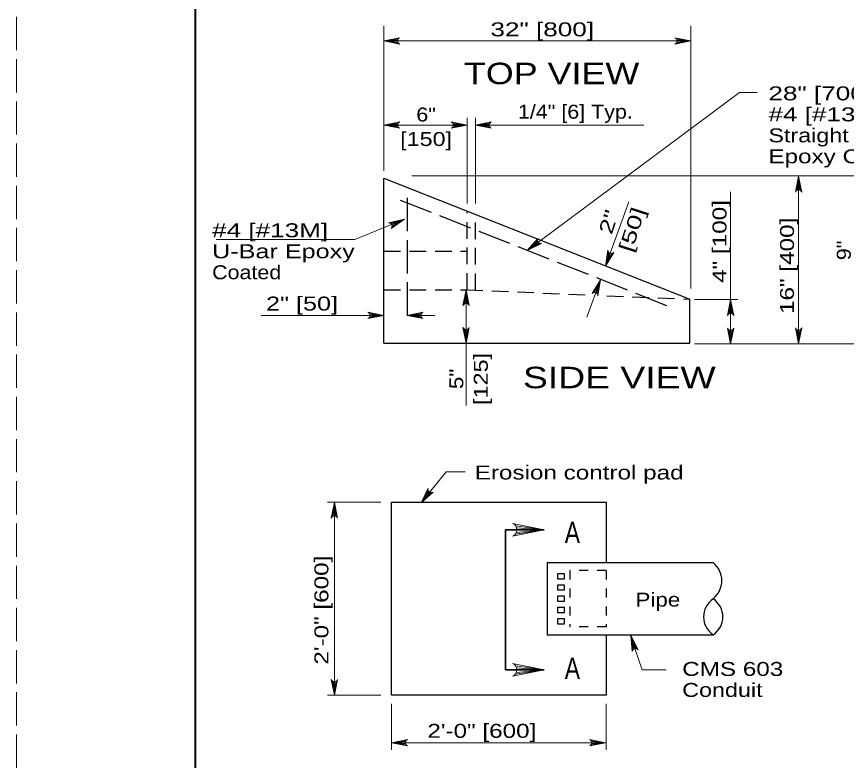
# Model space of a CAD drawing. Extents: x 1083.1 to 1117.1, y 697.4 to 741.4.
# Drawn here: x 1083.13 to 1092.41, y 728.79 to 737.11 of the extents above; entities that cross this region are included whole.
import ezdxf
from ezdxf.enums import TextEntityAlignment as Align

# ---------------------------------------------------------------- set-up
doc = ezdxf.new("R2010")
doc.units = 0
doc.header["$LTSCALE"] = 0.062
for name, pattern in [('LONG_DASHED', [7.5, 6, -1.5]), ('MEDIUM_DASHED', [4.5, 3, -1.5]), ('SHORT_DASHED', [2.7, 1.5, -1.2])]:
    doc.linetypes.add(name, pattern=pattern)
doc.layers.add('1', color=7, linetype='Continuous', lineweight=13)

msp = doc.modelspace()

# ---------------------------------------------------------------- linework, layer by layer
at = {"layer": '1'}
for p, q in [((1087.23608, 735.38583), (1087.23608, 737.00783)), ((1090.66825, 736.05733), (1090.66825, 737.00783)), ((1087.39633, 736.86058), (1087.23608, 736.83817)), ((1087.39092, 736.8495), (1087.23608, 736.83817)), ((1087.38925, 736.83817), (1087.23608, 736.83817)), ((1087.39208, 736.82383), (1087.23608, 736.83817)), ((1087.39825, 736.81342), (1087.23608, 736.83817)), ((1090.66825, 736.83817), (1087.23608, 736.83817)), ((1090.50608, 736.81342), (1090.66825, 736.83817)), ((1090.508, 736.86058), (1090.66825, 736.83817)), ((1090.51225, 736.82383), (1090.66825, 736.83817)), ((1090.51342, 736.8495), (1090.66825, 736.83817)), ((1090.51508, 736.83817), (1090.66825, 736.83817)), ((1088.16583, 735.02092), (1088.16583, 735.97592)), ((1088.2595, 735.02092), (1088.2595, 735.97592)), ((1090.66825, 734.07008), (1090.66825, 736.05733)), ((1087.39633, 735.91967), (1087.23608, 735.89725)), ((1087.39092, 735.90858), (1087.23608, 735.89725)), ((1087.38925, 735.89725), (1087.23608, 735.89725)), ((1087.39208, 735.88283), (1087.23608, 735.89725)), ((1087.39825, 735.87242), (1087.23608, 735.89725)), ((1088.16583, 735.89725), (1087.23608, 735.89725)), ((1088.00375, 735.87242), (1088.16583, 735.89725)), ((1088.00558, 735.91967), (1088.16583, 735.89725)), ((1088.00983, 735.88283), (1088.16583, 735.89725)), ((1088.01108, 735.90858), (1088.16583, 735.89725)), ((1088.01267, 735.89725), (1088.16583, 735.89725)), ((1088.41975, 735.91967), (1088.2595, 735.89725)), ((1088.41433, 735.90858), (1088.2595, 735.89725)), ((1090.14192, 735.89725), (1088.2595, 735.89725)), ((1088.41267, 735.89725), (1088.2595, 735.89725)), ((1088.4155, 735.88283), (1088.2595, 735.89725)), ((1088.42167, 735.87242), (1088.2595, 735.89725)), ((1091.85025, 735.16192), (1091.87508, 735.32408)), ((1091.86067, 735.16808), (1091.87508, 735.32408)), ((1091.87508, 733.452), (1091.87508, 735.32408)), ((1091.87508, 735.17092), (1091.87508, 735.32408)), ((1091.88642, 735.16925), (1091.87508, 735.32408)), ((1091.8975, 735.16383), (1091.87508, 735.32408)), ((1091.11467, 733.44867), (1091.11467, 735.15117)), ((1089.71325, 734.32042), (1089.97475, 735.03883)), ((1086.90858, 734.61625), (1087.46417, 734.84283)), ((1087.3055, 734.8015), (1087.46417, 734.84283)), ((1087.31525, 734.79433), (1087.46417, 734.84283)), ((1087.3235, 734.78225), (1087.46417, 734.84283)), ((1087.32592, 734.75892), (1087.46417, 734.84283)), ((1087.3265, 734.77125), (1087.46417, 734.84283)), ((1087.36917, 734.804), (1087.46417, 734.84283)), ((1086.90858, 734.61625), (1085.359, 734.61625)), ((1088.95258, 734.6085), (1088.83692, 734.49542)), ((1088.95475, 734.59633), (1088.83692, 734.49542)), ((1088.96017, 734.58625), (1088.83692, 734.49542)), ((1088.971, 734.57633), (1088.83692, 734.49542)), ((1088.98208, 734.57167), (1088.83692, 734.49542)), ((1089.7485, 734.47833), (1089.71325, 734.32042)), ((1089.757, 734.46933), (1089.71325, 734.32042)), ((1089.767, 734.46383), (1089.71325, 734.32042)), ((1089.79333, 734.4635), (1089.71325, 734.32042)), ((1089.7815, 734.46142), (1089.71325, 734.32042)), ((1089.5055, 733.75), (1089.65717, 734.16658)), ((1089.579, 734.02242), (1089.65717, 734.16658)), ((1089.59083, 734.02467), (1089.65717, 734.16658)), ((1089.60533, 734.02242), (1089.65717, 734.16658)), ((1089.61542, 734.017), (1089.65717, 734.16658)), ((1089.624, 734.00817), (1089.65717, 734.16658)), ((1088.13058, 733.89283), (1088.15542, 734.055)), ((1088.141, 733.899), (1088.15542, 734.055)), ((1088.15542, 732.76133), (1088.15542, 734.055)), ((1088.15542, 733.90183), (1088.15542, 734.055)), ((1088.16675, 733.90017), (1088.15542, 734.055)), ((1088.17783, 733.89475), (1088.15542, 734.055)), ((1091.19608, 733.9465), (1090.709, 733.9465)), ((1091.08992, 733.7825), (1091.11467, 733.94467)), ((1091.10033, 733.78867), (1091.11467, 733.94467)), ((1091.11467, 733.7915), (1091.11467, 733.94467)), ((1091.126, 733.78983), (1091.11467, 733.94467)), ((1091.13717, 733.78442), (1091.11467, 733.94467)), ((1087.23458, 733.76908), (1085.86383, 733.76908)), ((1087.0725, 733.74425), (1087.23458, 733.76908)), ((1087.07433, 733.7915), (1087.23458, 733.76908)), ((1087.07858, 733.75467), (1087.23458, 733.76908)), ((1087.07975, 733.78042), (1087.23458, 733.76908)), ((1087.08142, 733.76908), (1087.23458, 733.76908)), ((1087.65583, 733.7915), (1087.49558, 733.76908)), ((1087.65042, 733.78042), (1087.49558, 733.76908)), ((1087.64875, 733.76908), (1087.49558, 733.76908)), ((1087.65158, 733.75467), (1087.49558, 733.76908)), ((1087.65775, 733.74425), (1087.49558, 733.76908)), ((1087.80492, 733.76908), (1087.49683, 733.76908)), ((1088.133, 733.618), (1088.15542, 733.45775)), ((1088.14408, 733.6125), (1088.15542, 733.45775)), ((1088.18017, 733.61983), (1088.15542, 733.45775)), ((1088.16975, 733.61375), (1088.15542, 733.45775)), ((1088.15542, 733.61092), (1088.15542, 733.45775)), ((1091.09225, 733.60892), (1091.11467, 733.44867)), ((1091.10342, 733.6035), (1091.11467, 733.44867)), ((1091.1395, 733.61083), (1091.11467, 733.44867)), ((1091.12908, 733.60467), (1091.11467, 733.44867)), ((1091.11467, 733.60183), (1091.11467, 733.44867)), ((1091.85267, 733.61225), (1091.87508, 733.452)), ((1091.86375, 733.60683), (1091.87508, 733.452)), ((1091.89983, 733.61417), (1091.87508, 733.452)), ((1091.8895, 733.608), (1091.87508, 733.452)), ((1091.87508, 733.60517), (1091.87508, 733.452)), ((1092.86575, 733.45017), (1090.709, 733.45017)), ((1087.65083, 731.67367), (1087.93242, 732.01783)), ((1088.14383, 732.01783), (1087.93242, 732.01783)), ((1087.72983, 731.81492), (1087.65083, 731.67367)), ((1087.73542, 731.80392), (1087.65083, 731.67367)), ((1087.74342, 731.79575), (1087.65083, 731.67367)), ((1087.75658, 731.78925), (1087.65083, 731.67367)), ((1087.76858, 731.78792), (1087.65083, 731.67367)), ((1087.20192, 731.6795), (1086.60317, 731.6795)), ((1086.65708, 731.51742), (1086.68183, 731.6795)), ((1086.6675, 731.5235), (1086.68183, 731.6795)), ((1086.68183, 731.52633), (1086.68183, 731.6795)), ((1086.69317, 731.52467), (1086.68183, 731.6795)), ((1086.70425, 731.51925), (1086.68183, 731.6795)), ((1088.70517, 731.32175), (1089.02942, 731.37133)), ((1088.70892, 731.41617), (1089.02942, 731.37133)), ((1088.71742, 731.34258), (1089.02942, 731.37133)), ((1088.71975, 731.394), (1089.02942, 731.37133)), ((1088.72308, 731.37133), (1089.02942, 731.37133)), ((1089.99067, 730.19533), (1090.12567, 729.80725)), ((1090.03975, 730.0425), (1089.99742, 730.18967)), ((1090.02667, 730.03583), (1089.99742, 730.18967)), ((1090.01842, 730.027), (1089.99742, 730.18967)), ((1090.05108, 730.04408), (1089.99742, 730.18967)), ((1090.06325, 730.04192), (1089.99742, 730.18967)), ((1088.70892, 729.85033), (1089.02942, 729.8055)), ((1088.70517, 729.756), (1089.02942, 729.8055)), ((1088.71742, 729.77675), (1089.02942, 729.8055)), ((1088.71975, 729.82817), (1089.02942, 729.8055)), ((1088.72308, 729.8055), (1089.02942, 729.8055)), ((1090.39208, 729.80725), (1090.12567, 729.80725)), ((1086.65942, 729.681), (1086.68183, 729.52075)), ((1086.6705, 729.67558), (1086.68183, 729.52075)), ((1086.70667, 729.68292), (1086.68183, 729.52075)), ((1086.69625, 729.67675), (1086.68183, 729.52075)), ((1086.68183, 729.67392), (1086.68183, 729.52075)), ((1087.20192, 729.52075), (1086.60317, 729.52075)), ((1087.32133, 729.42533), (1087.32133, 728.91242)), ((1089.72025, 729.42533), (1089.72025, 728.91242)), ((1087.48158, 729.0135), (1087.32133, 728.99108)), ((1089.555, 729.0135), (1089.71525, 728.99108)), ((1087.47617, 729.00242), (1087.32133, 728.99108)), ((1087.32133, 728.99108), (1089.71892, 728.99108)), ((1087.4745, 728.99108), (1087.32133, 728.99108)), ((1087.47733, 728.97667), (1087.32133, 728.99108)), ((1087.4835, 728.96633), (1087.32133, 728.99108)), ((1089.55317, 728.96633), (1089.71525, 728.99108)), ((1089.55925, 728.97667), (1089.71525, 728.99108)), ((1089.5605, 729.00242), (1089.71525, 728.99108)), ((1089.56208, 728.99108), (1089.71525, 728.99108))]:
    msp.add_line(p, q, dxfattribs=at)
at = {"layer": '1', "lineweight": 25}
for p, q in [((1087.23608, 733.45775), (1087.23608, 735.3015)), ((1090.65808, 733.45775), (1090.65808, 733.94942)), ((1087.23608, 733.45775), (1090.65808, 733.45775)), ((1089.72025, 731.6795), (1089.72025, 731.00492)), ((1089.06167, 731.00492), (1090.91967, 731.00492)), ((1089.06167, 731.00492), (1089.06167, 730.19533)), ((1089.06167, 730.19533), (1090.91967, 730.19533)), ((1089.72025, 730.19533), (1089.72025, 729.52075)), ((1089.72025, 729.52075), (1087.32133, 729.52075))]:
    msp.add_line(p, q, dxfattribs=at)
at = {"layer": '1', "linetype": 'LONG_DASHED', "lineweight": 25}
for p, q in [((1090.40133, 733.87725), (1087.398, 735.06392)), ((1087.49683, 735.08242), (1087.49683, 733.721))]:
    msp.add_line(p, q, dxfattribs=at)
at = {"layer": '1', "linetype": 'MEDIUM_DASHED', "lineweight": 25}
for p, q in [((1088.16575, 734.05458), (1088.16575, 734.92175)), ((1088.2595, 734.05067), (1088.2595, 734.897)), ((1087.23608, 734.4865), (1088.157, 734.4865)), ((1089.72883, 733.98867), (1090.65808, 733.94942))]:
    msp.add_line(p, q, dxfattribs=at)
at = {"layer": '1', "lineweight": 35}
for p, q in [((1088.59675, 729.8055), (1088.59675, 731.37133)), ((1089.02942, 731.37133), (1088.59675, 731.37133)), ((1089.02942, 729.8055), (1088.59675, 729.8055))]:
    msp.add_line(p, q, dxfattribs=at)
at = {"layer": '1', "linetype": 'SHORT_DASHED', "lineweight": 25}
for p, q in [((1089.72025, 730.91492), (1089.31383, 730.91492)), ((1089.31383, 730.91492), (1089.31383, 730.28533)), ((1089.72025, 730.91492), (1089.72025, 730.28533)), ((1089.72025, 730.28533), (1089.31383, 730.28533))]:
    msp.add_line(p, q, dxfattribs=at)
at = {"layer": '1', "linetype": 'LONG_DASHED'}
msp.add_lwpolyline([(1083.12642, 719.35408), (1117.12642, 719.35408), (1117.12642, 741.35408), (1083.12642, 741.35408)], close=True, dxfattribs=at)
at = {"layer": '1', "lineweight": 25}
for points in [[(1116.62642, 719.85408), (1085.12642, 719.85408), (1085.12642, 740.85408)], [(1087.23608, 735.3015), (1089.12075, 734.55683), (1090.65808, 733.94942)], [(1087.32133, 729.52075), (1087.32133, 731.6795), (1089.72025, 731.6795)]]:
    msp.add_lwpolyline(points, dxfattribs=at)
at = {"layer": '1', "lineweight": 40}
msp.add_lwpolyline([(1085.12642, 740.85408), (1116.62642, 740.85408), (1116.62642, 719.85408), (1085.12642, 719.85408)], close=True, dxfattribs=at)
msp.add_lwpolyline([(1085.12642, 740.85408), (1116.62642, 740.85408), (1116.62642, 719.85408), (1085.12642, 719.85408)], close=True, dxfattribs=at)
at = {"layer": '1'}
for points in [[(1087.41308, 736.80283), (1087.23608, 736.83817), (1087.41308, 736.87358)], [(1090.49125, 736.80283), (1090.66825, 736.83817), (1090.49125, 736.87358)], [(1088.83692, 734.49542), (1091.21417, 736.26033), (1091.41108, 736.26033)], [(1087.41308, 735.86183), (1087.23608, 735.89725), (1087.41308, 735.93267)], [(1087.98883, 735.86183), (1088.16583, 735.89725), (1087.98883, 735.93267)], [(1088.4365, 735.86183), (1088.2595, 735.89725), (1088.4365, 735.93267)], [(1087.54775, 735.32775), (1090.51608, 735.32775), (1092.9005, 735.32775)], [(1091.83967, 735.14708), (1091.87508, 735.32408), (1091.9105, 735.14708)], [(1087.28758, 734.80533), (1087.46417, 734.84283), (1087.31558, 734.74033)], [(1089.00033, 734.57192), (1088.83692, 734.49542), (1088.95833, 734.62892)], [(1089.8085, 734.47375), (1089.71325, 734.32042), (1089.74225, 734.49858)], [(1089.56392, 734.012), (1089.65717, 734.16658), (1089.63058, 733.988)], [(1088.12, 733.878), (1088.15542, 734.055), (1088.19075, 733.878)], [(1091.07933, 733.76767), (1091.11467, 733.94467), (1091.15008, 733.76767)], [(1087.05758, 733.73367), (1087.23458, 733.76908), (1087.05758, 733.80442)], [(1087.67258, 733.73367), (1087.49558, 733.76908), (1087.67258, 733.80442)], [(1088.19075, 733.63475), (1088.15542, 733.45775), (1088.12, 733.63475)], [(1091.15008, 733.62567), (1091.11467, 733.44867), (1091.07933, 733.62567)], [(1091.9105, 733.629), (1091.87508, 733.452), (1091.83967, 733.629)], [(1087.78608, 731.79333), (1087.65083, 731.67367), (1087.72967, 731.83608)], [(1086.6465, 731.5025), (1086.68183, 731.6795), (1086.71725, 731.5025)], [(1086.68183, 729.52075), (1086.68183, 730.45192), (1086.68183, 731.6795)], [(1088.67542, 731.30058), (1089.02942, 731.37133), (1088.67542, 731.44217)], [(1090.01233, 730.00983), (1089.99742, 730.18967), (1090.08033, 730.02942)], [(1088.67542, 729.73475), (1089.02942, 729.8055), (1088.67542, 729.87633)], [(1086.71725, 729.69775), (1086.68183, 729.52075), (1086.6465, 729.69775)], [(1087.49833, 728.95567), (1087.32133, 728.99108), (1087.49833, 729.0265)], [(1089.53825, 728.95567), (1089.71525, 728.99108), (1089.53825, 729.0265)]]:
    msp.add_lwpolyline(points, dxfattribs=at)
at = {"layer": '1', "linetype": 'MEDIUM_DASHED', "lineweight": 25}
msp.add_lwpolyline([(1087.23608, 734.055), (1088.157, 734.055), (1089.50292, 733.99817)], dxfattribs=at)
at = {"layer": '1', "linetype": 'SHORT_DASHED', "lineweight": 25}
for points in [[(1089.18075, 730.8835), (1089.25075, 730.8835), (1089.25075, 730.8205), (1089.18075, 730.8205)], [(1089.18075, 730.7575), (1089.25075, 730.7575), (1089.25075, 730.69458), (1089.18075, 730.69458)], [(1089.18075, 730.63158), (1089.25075, 730.63158), (1089.25075, 730.56867), (1089.18075, 730.56867)], [(1089.18075, 730.50567), (1089.25075, 730.50567), (1089.25075, 730.44275), (1089.18075, 730.44275)], [(1089.18075, 730.37975), (1089.25075, 730.37975), (1089.25075, 730.31683), (1089.18075, 730.31683)]]:
    msp.add_lwpolyline(points, close=True, dxfattribs=at)
at = {"layer": '1'}
for centre, radius, start, end in [((1087.42741, 736.83824), 0.0382, 112.08782, 247.91395), ((1090.47692, 736.83824), 0.0382, 292.08605, 67.91218), ((1087.42741, 735.89727), 0.0382, 112.08782, 247.91395), ((1087.97457, 735.89727), 0.0382, 292.08605, 67.91218), ((1088.4508, 735.89727), 0.0382, 112.08782, 247.91395), ((1091.8751, 735.1328), 0.0382, 22.08782, 157.91395), ((1087.28851, 734.76715), 0.0382, 315.38531, 91.21143), ((1088.99083, 734.60894), 0.0382, 148.49218, 284.31831), ((1089.78034, 734.49955), 0.0382, 181.5509, 317.37703), ((1089.59245, 733.98653), 0.0382, 2.30594, 138.13206), ((1088.15542, 733.86371), 0.0382, 22.08782, 157.91395), ((1087.04331, 733.76909), 0.0382, 292.08605, 67.91218), ((1087.6869, 733.76909), 0.0382, 112.08782, 247.91395), ((1091.11475, 733.75338), 0.0382, 22.08782, 157.91395), ((1088.15535, 733.64902), 0.0382, 202.08782, 337.91395), ((1091.11467, 733.63997), 0.0382, 202.08782, 337.91395), ((1091.87502, 733.64331), 0.0382, 202.08782, 337.91395), ((1087.76645, 731.82613), 0.0382, 164.90156, 300.72769), ((1086.6819, 731.48822), 0.0382, 22.08782, 157.91395), ((1088.64681, 731.37143), 0.0764, 292.08605, 67.91218), ((1090.05034, 730.00588), 0.0382, 38.14278, 173.9689), ((1088.64681, 729.80561), 0.0764, 292.08605, 67.91218), ((1086.68182, 729.71205), 0.0382, 202.08782, 337.91395), ((1087.51265, 728.99113), 0.0382, 112.08782, 247.91395), ((1089.52399, 728.99113), 0.0382, 292.08605, 67.91218)]:
    msp.add_arc(centre, radius, start, end, dxfattribs=at)
at = {"layer": '1', "lineweight": 25}
for centre, major_axis, start_param, end_param in [((1090.70506, 730.80252), (0.31085, 0), 5.4743674, 7.0920031), ((1091.09809, 730.39775), (-0.28709, 0), 5.3830944, 7.1832762), ((1090.74123, 730.39775), (0.28708, 0), 5.3830944, 7.1832762)]:
    msp.add_ellipse(centre, major_axis=major_axis, ratio=0.899905, start_param=start_param, end_param=end_param, dxfattribs=at)

# ---------------------------------------------------------------- texts
at = {"layer": '1'}
for s, height, width, p in [('32" [800]', 0.156, 1.4, (1088.4275, 736.88892)), ('TOP VIEW', 0.24, 1.25, (1088.13067, 736.35408)), ('28" [700]', 0.156, 1.4, (1091.53708, 736.17317)), ('#4 [#13M]', 0.156, 1.4, (1091.53708, 735.9385)), ('Straight Bar,', 0.156, 1.25, (1091.53708, 735.70383)), ('Epoxy Coated', 0.156, 1.3, (1091.53708, 735.46917)), ('#4 [#13M]', 0.156, 1.4, (1085.3135, 734.64233)), ('U-Bar Epoxy', 0.156, 1.35, (1085.3135, 734.40767)), ('Coated', 0.156, 1.15, (1085.3135, 734.173)), ('2" [50]', 0.156, 1.35, (1085.91708, 733.82283)), ('SIDE VIEW', 0.24, 1.3, (1088.7915, 732.95433)), ('Erosion control pad', 0.156, 1.3, (1088.25158, 731.934)), ('A', 0.24, 0.8, (1089.25842, 731.22208)), ('Pipe', 0.156, 1.2, (1090.04992, 730.51225)), ('A', 0.24, 0.8, (1089.25842, 729.70292)), ('CMS 603', 0.156, 1.3, (1090.57275, 729.7375)), ('Conduit', 0.156, 1.25, (1090.57275, 729.50283)), ('2\'-0" [600]', 0.156, 1.3, (1087.72208, 729.04533))]:
    msp.add_text(s, height=height, dxfattribs=dict(at, width=width)).set_placement(p)
for s, width, p in [('6"', 1.15, (1087.70767, 735.93658)), ('1/4" [6] Typ.', 1.15, (1089.37767, 735.96833)), ('[150]', 1.25, (1087.70767, 735.66258))]:
    msp.add_text(s, height=0.156, dxfattribs=dict(at, width=width)).set_placement(p, align=Align.CENTER)
for s, rotation, width, p in [('2"', 72.043, 1.4, (1089.82437, 734.78974)), ('[50]', 72.043, 1.45, (1090.08497, 734.70524)), ('4" [100]', 90, 1.3, (1091.06817, 734.595)), ('9"', 90, 1.15, (1092.45833, 734.495)), ('[125]', 90, 1.25, (1088.39783, 733.0585)), ('5"', 90, 1.2, (1088.12383, 733.05854))]:
    msp.add_text(s, height=0.156, rotation=rotation, dxfattribs=dict(at, width=width)).set_placement(p, align=Align.CENTER)
at = {"layer": '1', "width": 1.3}
for s, p in [('16" [400]', (1091.82333, 733.7845)), ('2\'-0" [600]', (1086.61433, 729.86392))]:
    msp.add_text(s, height=0.156, rotation=90, dxfattribs=at).set_placement(p)

doc.saveas('drawing.dxf')
